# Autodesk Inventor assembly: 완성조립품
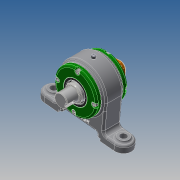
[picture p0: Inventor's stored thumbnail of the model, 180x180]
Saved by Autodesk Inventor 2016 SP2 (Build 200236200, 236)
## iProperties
Created: 2019-05
Part Number: 완성조립품
Document SubType Name: Assembly
Designer: EZ
Author: EZ
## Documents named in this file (13)
- Y:\490504V1017 강주호\490504v1017\완성조립품.iam
- Y:\490504V1017 강주호\490504v1017\본체.ipt
- Y:\490504V1017 강주호\490504v1017\개스킷.ipt
- Y:\490504V1017 강주호\490504v1017\그리스니플 M6.ipt
- 그리스니플  M6.ipt
- Y:\490504V1017 강주호\490504v1017\그리스니플개스킷.ipt
- Y:\490504V1017 강주호\490504v1017\베어링너트.ipt
- Y:\490504V1017 강주호\490504v1017\볼트 M4.ipt
- Y:\490504V1017 강주호\490504v1017\앵귤러 볼 베어링 7205.ipt
- Y:\490504V1017 강주호\490504v1017\오일 실 28 40 5 B.ipt
- Y:\490504V1017 강주호\490504v1017\축.ipt
- Y:\490504V1017 강주호\490504v1017\칼라.ipt
- Y:\490504V1017 강주호\490504v1017\커버.ipt
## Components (4 placed, 3 different names)
1. 개스킷:1
2. 그리스니플  M6:1
3. 그리스니플개스킷:1
4. 개스킷:2
